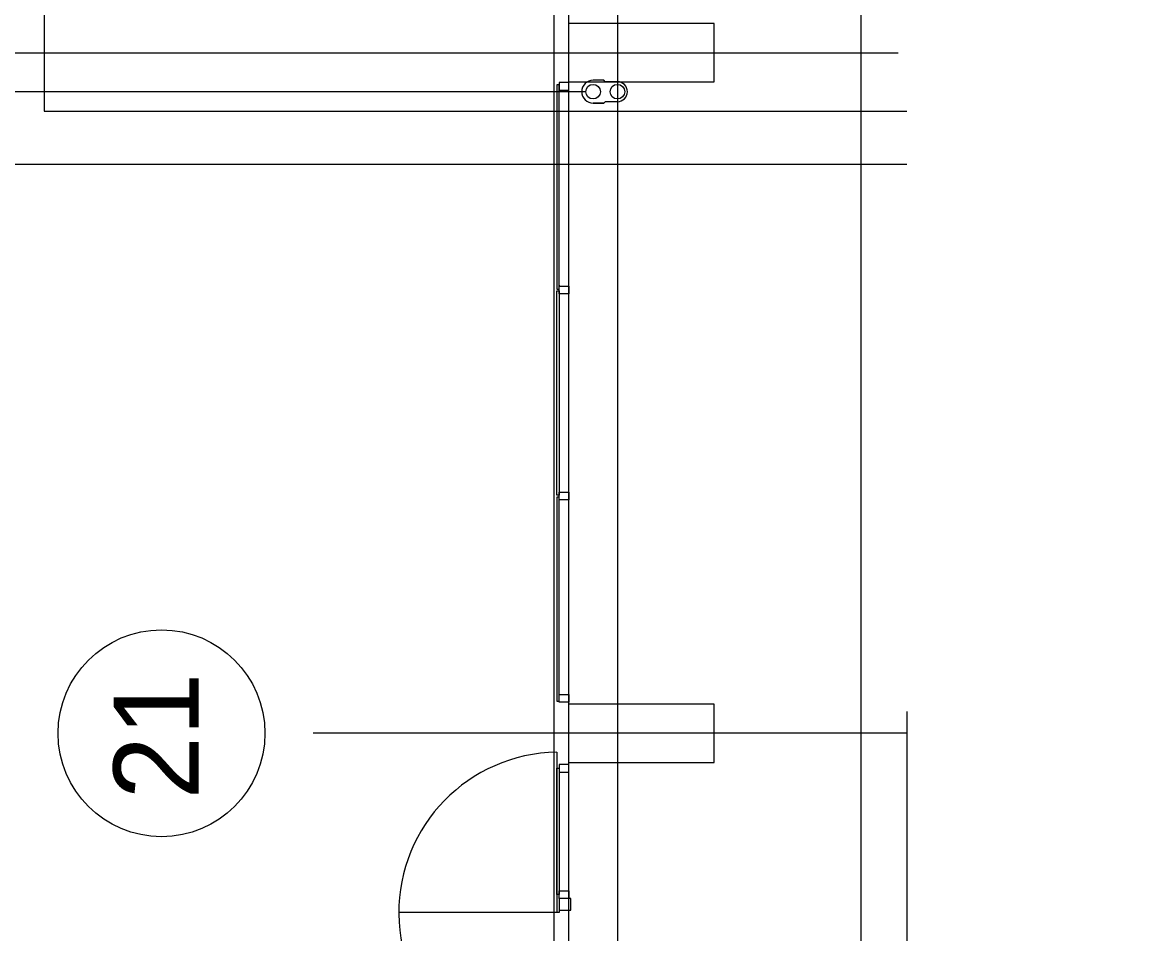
# Model space of a CAD drawing. Extents: x -264205 to -263659, y -1242401 to -1241986.
# Drawn here: x -263914.52 to -263902.98, y -1242218.94 to -1242209.57 of the extents above; entities that cross this region are included whole.
import ezdxf

# ---------------------------------------------------------------- set-up
doc = ezdxf.new("R2010")
doc.units = 0
for name, color, linetype in [('HESCON_OSI_STAVBY_KFA', 7, 'Continuous'), ('PROJEKT_OBRUBNIKY_KOMUNIKACIE', 7, 'Continuous'), ('RAM_NA_TLAC_2-1_1-250', 7, 'Continuous'), ('RAM_NA_TLAC_2-3_1-250', 7, 'Continuous'), ('SITUACIA_DSP_2D', 7, 'Continuous')]:
    doc.layers.add(name, color=color, linetype=linetype)

msp = doc.modelspace()

# ---------------------------------------------------------------- linework, layer by layer
at = {"layer": 'HESCON_OSI_STAVBY_KFA'}
for p, q in [((-263908.393, -1242083.237), (-263908.393, -1242246.707)), ((-263917.265, -1242209.882), (-263905.505, -1242209.882)), ((-263917.265, -1242209.882), (-263905.505, -1242209.882)), ((-263905.413, -1242216.882), (-263911.523, -1242216.882))]:
    msp.add_line(p, q, dxfattribs=at)
msp.add_circle((-263913.085, -1242216.882), 1.064, dxfattribs=at)
at = {"layer": 'PROJEKT_OBRUBNIKY_KOMUNIKACIE'}
msp.add_lwpolyline([(-263794.893, -1242227.382), (-263808.968, -1242241.457), (-263894.968, -1242241.457), (-263909.043, -1242227.382), (-263909.043, -1242196.333), (-263914.143, -1242196.333), (-263914.143, -1242132.433), (-263909.043, -1242132.433), (-263909.043, -1242101.382), (-263894.968, -1242087.307), (-263808.968, -1242087.307), (-263794.893, -1242101.382), (-263794.893, -1242227.382)], dxfattribs=at)
at = {"layer": 'RAM_NA_TLAC_2-1_1-250'}
msp.add_line((-263905.413, -1242216.657), (-263905.413, -1242219.157), dxfattribs=at)
at = {"layer": 'RAM_NA_TLAC_2-3_1-250'}
msp.add_lwpolyline([(-263980.139, -1242275.511), (-263980.139, -1241985.511), (-263905.889, -1241985.511), (-263905.889, -1242275.511)], close=True, dxfattribs=at)
at = {"layer": 'SITUACIA_DSP_2D'}
for p, q in [((-263914.293, -1242175.482), (-263914.293, -1242210.482)), ((-263909.043, -1242227.382), (-263909.043, -1242196.333)), ((-263908.893, -1242226.995), (-263908.893, -1242203.332)), ((-263907.398, -1242209.582), (-263908.898, -1242209.582)), ((-263908.898, -1242209.582), (-263908.898, -1242210.182)), ((-263907.398, -1242210.182), (-263907.398, -1242209.582)), ((-263909.018, -1242210.212), (-263909.018, -1242212.312)), ((-263908.993, -1242210.212), (-263909.018, -1242210.212)), ((-263908.893, -1242210.187), (-263908.993, -1242210.187)), ((-263908.993, -1242210.187), (-263908.993, -1242210.227)), ((-263908.993, -1242212.312), (-263908.993, -1242210.212)), ((-263908.993, -1242210.227), (-263908.993, -1242210.267)), ((-263908.898, -1242210.182), (-263907.398, -1242210.182)), ((-263908.893, -1242210.267), (-263908.893, -1242210.187)), ((-263908.532, -1242210.165), (-263908.643, -1242210.165)), ((-263908.518, -1242210.179), (-263908.532, -1242210.165)), ((-263908.393, -1242210.179), (-263908.518, -1242210.179)), ((-263908.718, -1242210.282), (-263918.714, -1242210.282)), ((-263908.993, -1242210.267), (-263908.893, -1242210.267)), ((-263914.293, -1242210.482), (-263905.413, -1242210.482)), ((-263908.643, -1242210.399), (-263908.532, -1242210.399)), ((-263908.532, -1242210.399), (-263908.643, -1242210.399)), ((-263908.518, -1242210.385), (-263908.532, -1242210.399)), ((-263908.393, -1242210.385), (-263908.518, -1242210.385)), ((-263905.413, -1242211.032), (-263921.351, -1242211.032)), ((-263909.018, -1242212.312), (-263908.993, -1242212.312)), ((-263909.018, -1242214.432), (-263909.018, -1242212.332)), ((-263909.018, -1242212.332), (-263908.993, -1242212.332)), ((-263908.993, -1242212.272), (-263908.993, -1242212.282)), ((-263908.993, -1242212.362), (-263908.993, -1242212.272)), ((-263908.993, -1242212.282), (-263908.893, -1242212.282)), ((-263908.993, -1242212.332), (-263908.993, -1242214.432)), ((-263908.893, -1242212.282), (-263908.893, -1242212.362)), ((-263908.893, -1242212.362), (-263908.993, -1242212.362)), ((-263908.993, -1242214.442), (-263908.993, -1242214.402)), ((-263908.993, -1242214.402), (-263908.893, -1242214.402)), ((-263908.893, -1242214.402), (-263908.893, -1242214.482)), ((-263908.993, -1242214.432), (-263909.018, -1242214.432)), ((-263909.018, -1242214.452), (-263909.018, -1242216.552)), ((-263908.993, -1242214.452), (-263909.018, -1242214.452)), ((-263908.993, -1242214.482), (-263908.993, -1242214.442)), ((-263908.993, -1242216.552), (-263908.993, -1242214.452)), ((-263908.893, -1242214.482), (-263908.993, -1242214.482)), ((-263908.993, -1242216.522), (-263908.993, -1242216.482)), ((-263908.993, -1242216.482), (-263908.893, -1242216.482)), ((-263908.893, -1242216.482), (-263908.893, -1242216.562)), ((-263909.018, -1242216.552), (-263908.993, -1242216.552)), ((-263908.993, -1242216.562), (-263908.993, -1242216.522)), ((-263908.893, -1242216.562), (-263908.993, -1242216.562)), ((-263907.398, -1242216.582), (-263908.898, -1242216.582)), ((-263908.898, -1242216.582), (-263908.898, -1242217.182)), ((-263907.398, -1242217.182), (-263907.398, -1242216.582)), ((-263909.018, -1242217.077), (-263909.018, -1242218.727)), ((-263908.898, -1242217.182), (-263907.398, -1242217.182)), ((-263909.018, -1242218.542), (-263909.018, -1242217.242)), ((-263909.018, -1242217.242), (-263908.993, -1242217.242)), ((-263908.893, -1242217.202), (-263908.993, -1242217.202)), ((-263908.993, -1242217.202), (-263908.993, -1242217.242)), ((-263908.993, -1242217.242), (-263908.993, -1242218.542)), ((-263908.993, -1242217.242), (-263908.993, -1242217.282)), ((-263908.993, -1242217.282), (-263908.893, -1242217.282)), ((-263908.893, -1242217.282), (-263908.893, -1242217.202)), ((-263908.993, -1242218.542), (-263909.018, -1242218.542)), ((-263908.993, -1242218.542), (-263908.993, -1242218.502)), ((-263908.993, -1242218.502), (-263908.893, -1242218.502)), ((-263908.993, -1242218.582), (-263908.993, -1242218.542)), ((-263908.893, -1242218.502), (-263908.893, -1242218.582)), ((-263908.893, -1242218.582), (-263908.993, -1242218.582)), ((-263908.873, -1242218.582), (-263908.993, -1242218.582)), ((-263908.993, -1242218.582), (-263908.993, -1242218.702)), ((-263908.873, -1242218.702), (-263908.873, -1242218.582)), ((-263908.993, -1242218.727), (-263910.643, -1242218.727)), ((-263908.993, -1242218.702), (-263908.993, -1242218.727)), ((-263908.993, -1242218.702), (-263908.873, -1242218.702))]:
    msp.add_line(p, q, dxfattribs=at)
for centre in [(-263908.643, -1242210.282), (-263908.393, -1242210.282)]:
    msp.add_circle(centre, 0.075, dxfattribs=at)
for centre, radius, start, end in [((-263908.643, -1242210.282), 0.117, 90, 270), ((-263908.393, -1242210.282), 0.103, 270, 90), ((-263908.993, -1242218.727), 1.65, 90.8682, 270)]:
    msp.add_arc(centre, radius, start, end, dxfattribs=at)

# ---------------------------------------------------------------- texts
at = {"layer": 'HESCON_OSI_STAVBY_KFA'}
msp.add_text('21', height=0.875, rotation=90, dxfattribs=at).set_placement((-263912.704, -1242217.562))

doc.saveas('drawing.dxf')
